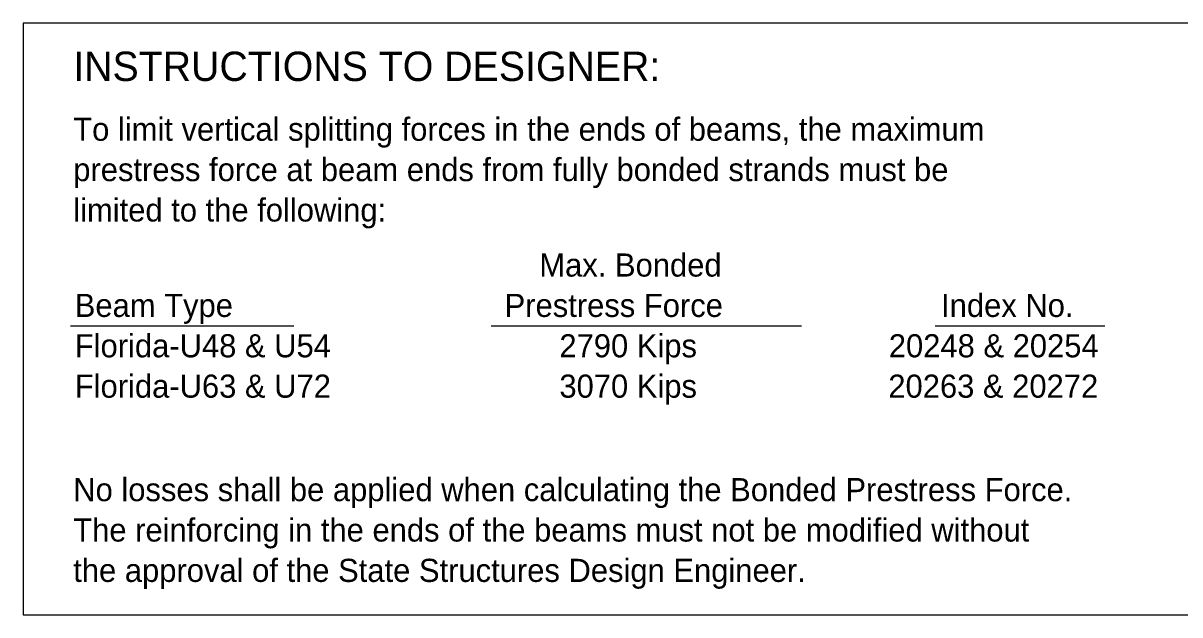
# Model space of a CAD drawing. Extents: x 120784.3 to 120844.8, y 120560 to 120604.3.
# Drawn here: x 120815.37 to 120822.93, y 120572.26 to 120576.13 of the extents above; entities that cross this region are included whole.
import ezdxf

# ---------------------------------------------------------------- set-up
doc = ezdxf.new("R2010")
doc.units = 0
doc.layers.add('PlotBorder_dp', color=7, linetype='Continuous')
doc.layers.add('SheetBorder_dp', color=7, linetype='Continuous')

msp = doc.modelspace()

# ---------------------------------------------------------------- linework, layer by layer
at = {"layer": 'PlotBorder_dp'}
for p, q in [((120815.6793, 120574.1507), (120817.1385, 120574.1507)), ((120818.4278, 120574.1507), (120820.4563, 120574.1507)), ((120821.3301, 120574.1507), (120822.4387, 120574.1507))]:
    msp.add_line(p, q, dxfattribs=at)
msp.add_lwpolyline([(120815.3693, 120572.2599), (120825.0769, 120572.2599), (120825.0769, 120576.129), (120815.3693, 120576.129)], close=True, dxfattribs=at)

# ---------------------------------------------------------------- texts
for s, p in [('To limit vertical splitting forces in the ends of beams, the maximum ', (120815.6968, 120575.3598)), ('prestress force at beam ends from fully bonded strands must be ', (120815.6968, 120575.0958)), ('limited to the following:', (120815.6968, 120574.8318)), ('Max. Bonded', (120818.743, 120574.4718)), ('Beam Type', (120815.7067, 120574.2078)), ('Prestress Force', (120818.5162, 120574.2078)), ('Index No.', (120821.369, 120574.2078)), ('Florida-U48 & U54', (120815.7067, 120573.9438)), ('2790 Kips', (120818.8743, 120573.9438)), ('20248 & 20254', (120821.0272, 120573.9438)), ('Florida-U63 & U72', (120815.7067, 120573.6798)), ('3070 Kips', (120818.8743, 120573.6798)), ('20263 & 20272', (120821.0242, 120573.6798)), ('No losses shall be applied when calculating the Bonded Prestress Force.  ', (120815.6968, 120573.0033)), ('The reinforcing in the ends of the beams must not be modified without ', (120815.6968, 120572.7393)), ('the approval of the State Structures Design Engineer.', (120815.6968, 120572.4753))]:
    msp.add_text(s, height=0.1512, dxfattribs=at).set_placement(p)
at = {"layer": 'SheetBorder_dp'}
msp.add_text('INSTRUCTIONS TO DESIGNER:', height=0.192, dxfattribs=at).set_placement((120815.6968, 120575.7507))

doc.saveas('drawing.dxf')
